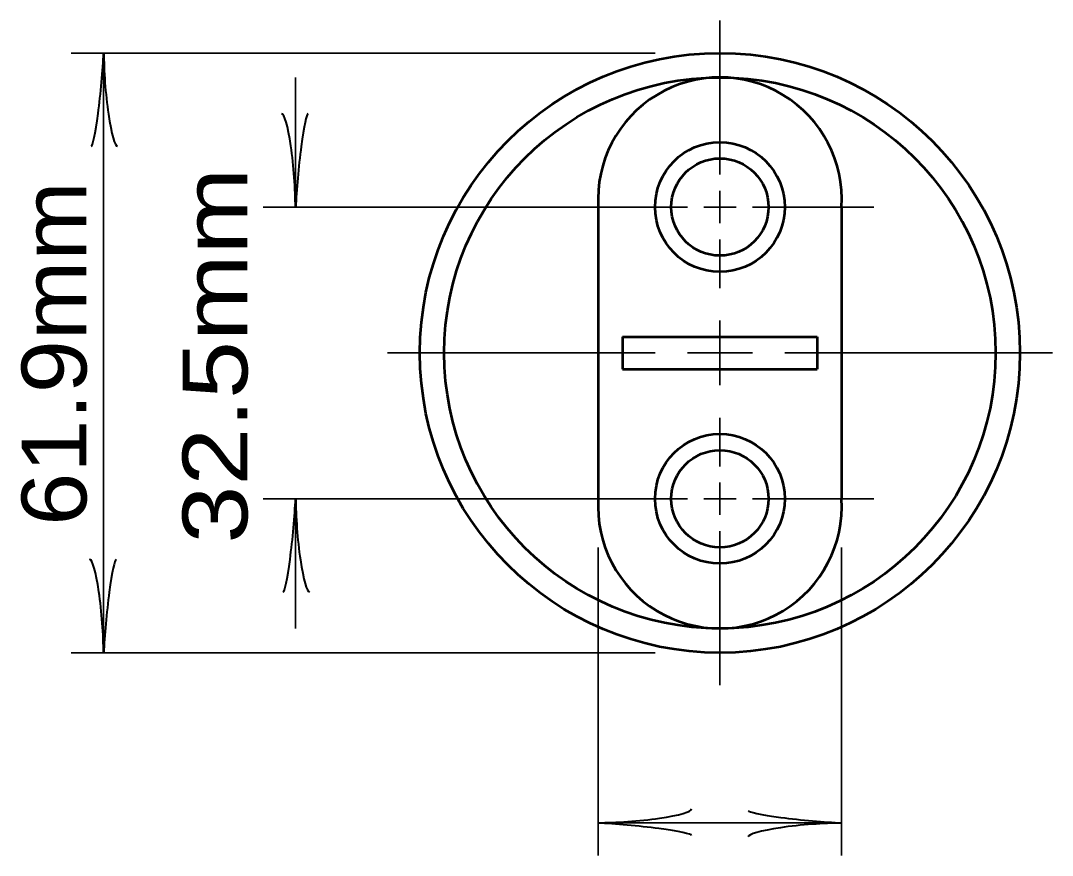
# Model space of a CAD drawing. Extents: x -32 to 824, y -6 to 538.
# Drawn here: x 307.67 to 345.84, y 406.9 to 437.8 of the extents above; entities that cross this region are included whole.
import ezdxf

# ---------------------------------------------------------------- set-up
doc = ezdxf.new("R2010")
doc.units = 0
doc.header["$LTSCALE"] = 1.1
doc.layers.add('1', color=7, linetype='Continuous', lineweight=53)

msp = doc.modelspace()

# ---------------------------------------------------------------- linework, layer by layer
at = {"layer": '1', "lineweight": 35}
for p, q in [((333.536, 437.796), (333.536, 432.096)), ((331.136, 436.596), (309.536, 436.596)), ((310.736, 436.596), (310.736, 414.396)), ((317.839, 435.696), (317.839, 430.896)), ((333.536, 431.496), (333.536, 430.296)), ((316.639, 430.896), (332.336, 430.896)), ((332.936, 430.896), (334.136, 430.896)), ((334.736, 430.896), (339.236, 430.896)), ((333.536, 429.696), (333.536, 427.896)), ((321.236, 425.496), (331.136, 425.496)), ((335.936, 425.496), (345.836, 425.496)), ((333.536, 423.096), (333.536, 421.296)), ((333.536, 420.696), (333.536, 419.496)), ((316.639, 420.096), (332.336, 420.096)), ((317.839, 420.096), (317.839, 415.296)), ((332.936, 420.096), (334.136, 420.096)), ((334.736, 420.096), (339.236, 420.096)), ((333.536, 418.896), (333.536, 413.196)), ((329.036, 418.296), (329.036, 406.896)), ((338.036, 418.296), (338.036, 406.896)), ((331.136, 414.396), (309.536, 414.396)), ((329.036, 408.096), (338.036, 408.096))]:
    msp.add_line(p, q, dxfattribs=at)
at = {"layer": '1'}
for p, q in [((329.036, 430.896), (329.036, 425.496)), ((338.036, 430.896), (338.036, 425.496)), ((329.936, 426.096), (333.536, 426.096)), ((329.936, 426.096), (329.936, 424.896)), ((333.536, 426.096), (337.136, 426.096)), ((337.136, 426.096), (337.136, 424.896)), ((329.036, 425.496), (329.036, 420.096)), ((338.036, 425.496), (338.036, 420.096)), ((329.936, 424.896), (333.536, 424.896)), ((333.536, 424.896), (337.136, 424.896))]:
    msp.add_line(p, q, dxfattribs=at)
at = {"layer": '1', "lineweight": 35}
for points in [[(333.536, 426.696), (333.536, 425.496), (333.536, 424.296)], [(332.336, 425.496), (333.536, 425.496), (334.736, 425.496)]]:
    msp.add_lwpolyline(points, dxfattribs=at)
at = {"layer": '1'}
for centre, radius in [((333.536, 425.496), 11.1), ((333.536, 425.496), 10.2), ((333.536, 430.896), 2.4), ((333.536, 430.896), 1.8), ((333.536, 420.096), 2.4), ((333.536, 420.096), 1.8)]:
    msp.add_circle(centre, radius, dxfattribs=at)
for centre, start, end in [((333.536, 431.187), 356.3048, 183.6952), ((333.536, 419.805), 176.3048, 3.6952)]:
    msp.add_arc(centre, 4.509, start, end, dxfattribs=at)
at = {"layer": '1', "lineweight": 40}
for centre, major_axis, ratio, start_param, end_param in [((310.482, 435.251), (0.211, 2.108), 0.07063, 3.140715, 5.41811), ((310.482, 435.251), (0.211, 2.108), 0.07063, 3.140715, 5.41811), ((311.068, 435.287), (-0.187, 2.143), 0.122415, 0.896353, 3.141593), ((311.068, 435.287), (-0.187, 2.143), 0.122415, 0.896353, 3.141593), ((317.507, 432.206), (0.187, -2.143), 0.122415, 0.896353, 3.141593), ((318.092, 432.241), (-0.211, -2.108), 0.07063, 3.140715, 5.41811), ((317.585, 418.751), (0.211, 2.108), 0.07063, 3.140715, 5.41811), ((318.17, 418.787), (-0.187, 2.143), 0.122415, 0.896353, 3.141593), ((310.405, 415.706), (0.187, -2.143), 0.122415, 0.896353, 3.141593), ((310.99, 415.741), (-0.211, -2.108), 0.07063, 3.140715, 5.41811), ((330.346, 408.428), (-2.143, -0.187), 0.122415, 0.896353, 3.141593), ((330.346, 408.428), (-2.143, -0.187), 0.122415, 0.896353, 3.141593), ((336.692, 408.35), (2.108, -0.211), 0.07063, 3.140715, 5.41811), ((330.381, 407.842), (-2.108, 0.211), 0.07063, 3.140715, 5.41811), ((330.381, 407.842), (-2.108, 0.211), 0.07063, 3.140715, 5.41811), ((336.727, 407.765), (2.143, 0.187), 0.122415, 0.896353, 3.141593)]:
    msp.add_ellipse(centre, major_axis=major_axis, ratio=ratio, start_param=start_param, end_param=end_param, dxfattribs=at)

# ---------------------------------------------------------------- texts
at = {"layer": '1'}
for s, width, p in [('32.5mm', 1.2, (316.056, 418.439)), ('61.9mm', 1.1, (310.101, 419.098))]:
    msp.add_text(s, height=2.4, rotation=90, dxfattribs=dict(at, width=width)).set_placement(p)

doc.saveas('drawing.dxf')
